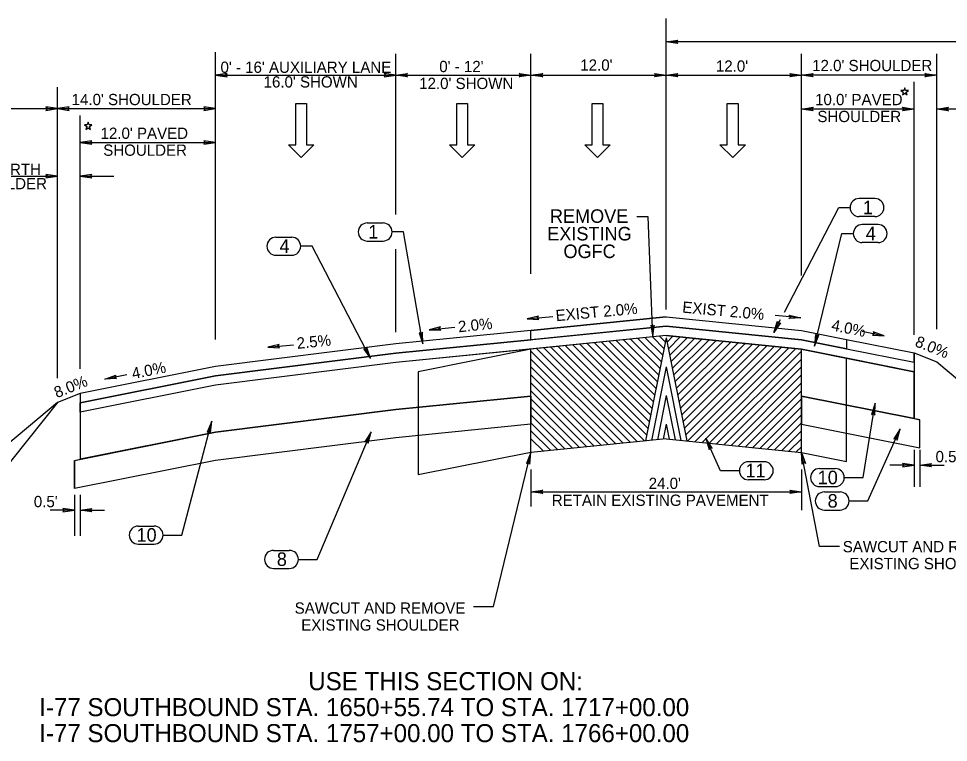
# Model space of a CAD drawing. Extents: x 2003207 to 2014043, y 843846 to 860154.
# Drawn here: x 2013658.4 to 2013740.9, y 844586.8 to 844651 of the extents above; entities that cross this region are included whole.
import ezdxf

# ---------------------------------------------------------------- set-up
doc = ezdxf.new("R2010")
doc.units = 0
for name, color, linetype in [('RD_EX_Road', 7, 'Continuous'), ('RD_EX_Road_txCode', 7, 'Continuous'), ('RD_QTY_Base_Course', 7, 'Continuous'), ('RD_QTY_ConcPave', 7, 'Continuous'), ('RD_QTY_Intermediate', 7, 'Continuous'), ('RD_QTY_PermVeg', 7, 'Continuous'), ('RD_QTY_Surf_Course', 7, 'Continuous'), ('RD_TX_Misc2', 7, 'Continuous'), ('RD_TX_TypSect', 7, 'Continuous')]:
    doc.layers.add(name, color=color, linetype=linetype)

msp = doc.modelspace()

# ---------------------------------------------------------------- linework, layer by layer
at = {"layer": 'RD_EX_Road'}
for p, q in [((2013709.505, 844622.215), (2013714.742, 844616.978)), ((2013710.148, 844622.279), (2013714.86, 844617.567)), ((2013710.79, 844622.344), (2013714.978, 844618.156)), ((2013711.433, 844622.408), (2013715.096, 844618.745)), ((2013712.076, 844622.472), (2013715.214, 844619.335)), ((2013712.719, 844622.536), (2013715.332, 844619.924)), ((2013713.362, 844622.601), (2013715.449, 844620.513)), ((2013714.005, 844622.665), (2013715.567, 844621.102)), ((2013715.875, 844622.64), (2013714.047, 844613.503)), ((2013714.647, 844622.729), (2013715.685, 844621.692)), ((2013715.29, 844622.794), (2013715.803, 844622.281)), ((2013715.875, 844622.852), (2013719.031, 844622.536)), ((2013715.875, 844622.64), (2013717.702, 844613.503)), ((2013716.46, 844622.794), (2013715.947, 844622.281)), ((2013717.102, 844622.729), (2013716.065, 844621.692)), ((2013717.745, 844622.665), (2013716.183, 844621.102)), ((2013718.388, 844622.601), (2013716.3, 844620.513)), ((2013719.031, 844622.536), (2013716.418, 844619.924)), ((2013719.674, 844622.472), (2013716.536, 844619.335)), ((2013720.317, 844622.408), (2013716.654, 844618.745)), ((2013720.959, 844622.344), (2013716.772, 844618.156)), ((2013721.602, 844622.279), (2013716.89, 844617.567)), ((2013722.245, 844622.215), (2013717.007, 844616.978)), ((2013703.875, 844621.652), (2013693.875, 844619.652)), ((2013706.291, 844621.894), (2013703.875, 844621.652)), ((2013703.875, 844612.485), (2013703.875, 844621.652)), ((2013703.875, 844621.481), (2013712.053, 844613.303)), ((2013704.362, 844621.701), (2013712.696, 844613.367)), ((2013705.005, 844621.765), (2013713.338, 844613.432)), ((2013705.648, 844621.829), (2013713.981, 844613.496)), ((2013706.291, 844621.894), (2013714.153, 844614.031)), ((2013706.933, 844621.958), (2013714.271, 844614.62)), ((2013707.576, 844622.022), (2013714.387, 844615.212)), ((2013708.219, 844622.086), (2013714.505, 844615.801)), ((2013708.862, 844622.151), (2013714.623, 844616.39)), ((2013722.888, 844622.151), (2013717.125, 844616.388)), ((2013723.531, 844622.086), (2013717.243, 844615.799)), ((2013724.173, 844622.022), (2013717.361, 844615.21)), ((2013724.816, 844621.958), (2013717.479, 844614.62)), ((2013725.459, 844621.894), (2013717.597, 844614.031)), ((2013726.102, 844621.829), (2013717.769, 844613.496)), ((2013726.745, 844621.765), (2013718.411, 844613.432)), ((2013727.388, 844621.701), (2013719.054, 844613.367)), ((2013727.875, 844621.481), (2013719.697, 844613.303)), ((2013727.875, 844612.485), (2013727.875, 844621.652)), ((2013727.875, 844621.652), (2013731.875, 844620.852)), ((2013703.875, 844620.774), (2013711.41, 844613.239)), ((2013727.875, 844620.774), (2013720.34, 844613.239)), ((2013731.875, 844611.685), (2013731.875, 844620.852)), ((2013703.875, 844620.067), (2013710.767, 844613.175)), ((2013715.875, 844620.091), (2013714.568, 844613.555)), ((2013715.875, 844620.091), (2013717.182, 844613.555)), ((2013727.875, 844620.067), (2013720.983, 844613.175)), ((2013693.875, 844619.652), (2013693.875, 844610.485)), ((2013703.875, 844619.36), (2013710.124, 844613.11)), ((2013727.875, 844619.36), (2013721.626, 844613.11)), ((2013703.875, 844618.653), (2013709.481, 844613.046)), ((2013727.875, 844618.653), (2013722.268, 844613.046)), ((2013703.875, 844617.945), (2013708.839, 844612.982)), ((2013703.875, 844617.238), (2013708.196, 844612.917)), ((2013715.875, 844617.541), (2013715.088, 844613.607)), ((2013715.875, 844617.541), (2013716.662, 844613.607)), ((2013727.875, 844617.945), (2013722.911, 844612.982)), ((2013727.875, 844617.238), (2013723.554, 844612.917)), ((2013703.875, 844616.531), (2013707.553, 844612.853)), ((2013727.875, 844616.531), (2013724.197, 844612.853)), ((2013703.875, 844615.824), (2013706.91, 844612.789)), ((2013727.875, 844615.824), (2013724.84, 844612.789)), ((2013703.875, 844615.117), (2013706.267, 844612.725)), ((2013715.875, 844614.992), (2013715.608, 844613.659)), ((2013715.875, 844614.992), (2013716.142, 844613.659)), ((2013727.875, 844615.117), (2013725.482, 844612.725)), ((2013703.875, 844614.41), (2013705.624, 844612.66)), ((2013727.875, 844614.41), (2013726.125, 844612.66)), ((2013703.875, 844613.703), (2013704.982, 844612.596)), ((2013715.875, 844613.685), (2013703.875, 844612.485)), ((2013715.875, 844613.685), (2013727.875, 844612.485)), ((2013727.875, 844613.703), (2013726.768, 844612.596)), ((2013703.875, 844612.485), (2013693.875, 844610.485)), ((2013727.875, 844612.996), (2013727.411, 844612.532)), ((2013727.875, 844612.485), (2013731.875, 844611.685))]:
    msp.add_line(p, q, dxfattribs=at)
at = {"layer": 'RD_QTY_Base_Course'}
for p, q in [((2013691.875, 844616.285), (2013675.875, 844614.285)), ((2013703.875, 844614.985), (2013691.875, 844613.785)), ((2013727.875, 844614.985), (2013738.375, 844612.885)), ((2013737.875, 844615.485), (2013738.375, 844615.385)), ((2013738.375, 844612.885), (2013738.375, 844615.385)), ((2013738.375, 844612.885), (2013738.375, 844615.385)), ((2013675.875, 844614.285), (2013663.875, 844611.885)), ((2013691.875, 844613.785), (2013675.875, 844611.785)), ((2013738.375, 844612.885), (2013738.375, 844612.885)), ((2013738.375, 844612.885), (2013738.375, 844612.885)), ((2013738.375, 844612.885), (2013738.375, 844612.885)), ((2013663.375, 844611.785), (2013663.875, 844611.885)), ((2013675.875, 844611.785), (2013663.375, 844609.285)), ((2013663.375, 844611.785), (2013663.375, 844609.285))]:
    msp.add_line(p, q, dxfattribs=at)
msp.add_lwpolyline([(2013703.875, 844617.485), (2013703.875, 844614.985), (2013691.875, 844613.785), (2013675.875, 844611.785), (2013663.375, 844609.285), (2013663.375, 844611.785), (2013675.875, 844614.285), (2013691.875, 844616.285)], close=True, dxfattribs=at)
msp.add_lwpolyline([(2013738.375, 844615.385), (2013731.875, 844616.667), (2013727.875, 844617.485), (2013727.875, 844614.985), (2013738.375, 844612.885)], dxfattribs=at)
at = {"layer": 'RD_QTY_ConcPave'}
for p, q in [((2013703.875, 844621.652), (2013691.875, 844620.452)), ((2013703.875, 844621.652), (2013703.875, 844621.652)), ((2013737.875, 844621.319), (2013737.875, 844619.652)), ((2013691.875, 844620.452), (2013691.875, 844620.452)), ((2013737.875, 844615.485), (2013737.875, 844619.652)), ((2013703.875, 844617.485), (2013691.875, 844616.285)), ((2013691.875, 844616.285), (2013703.875, 844617.485)), ((2013727.875, 844617.485), (2013737.875, 844615.485)), ((2013663.875, 844616.052), (2013663.875, 844611.885))]:
    msp.add_line(p, q, dxfattribs=at)
for points in [[(2013703.875, 844617.485), (2013703.875, 844617.617), (2013703.875, 844618.324), (2013703.875, 844621.652)], [(2013691.875, 844620.452), (2013675.875, 844618.452), (2013663.875, 844616.052), (2013663.875, 844611.885), (2013675.875, 844614.285), (2013691.875, 844616.285)]]:
    msp.add_lwpolyline(points, dxfattribs=at)
msp.add_lwpolyline([(2013727.875, 844621.652), (2013737.875, 844619.652), (2013737.875, 844615.485), (2013727.875, 844617.485)], close=True, dxfattribs=at)
at = {"layer": 'RD_QTY_Intermediate'}
for p, q in [((2013715.875, 844622.852), (2013703.875, 844621.652)), ((2013715.875, 844622.852), (2013727.875, 844621.652)), ((2013703.875, 844621.652), (2013691.875, 844620.452)), ((2013727.875, 844621.652), (2013731.875, 844620.852)), ((2013731.875, 844620.852), (2013737.875, 844619.652)), ((2013691.875, 844620.452), (2013675.875, 844618.452)), ((2013737.875, 844620.485), (2013737.875, 844619.652)), ((2013675.875, 844618.452), (2013663.875, 844616.052)), ((2013663.875, 844616.885), (2013663.875, 844616.052))]:
    msp.add_line(p, q, dxfattribs=at)
msp.add_lwpolyline([(2013727.875, 844621.652), (2013715.875, 844622.852), (2013691.875, 844620.452), (2013675.875, 844618.452), (2013663.875, 844616.052), (2013663.875, 844616.885), (2013675.875, 844619.285), (2013691.875, 844621.285), (2013715.875, 844623.685), (2013727.875, 844622.485), (2013731.875, 844621.685), (2013737.875, 844620.485), (2013737.875, 844619.652), (2013731.875, 844620.852)], close=True, dxfattribs=at)
at = {"layer": 'RD_QTY_PermVeg'}
for p, q in [((2013737.875, 844621.319), (2013739.875, 844620.519)), ((2013739.875, 844620.519), (2013771.875, 844593.852)), ((2013663.875, 844617.719), (2013661.875, 844616.919)), ((2013661.875, 844616.919), (2013637.875, 844596.919)), ((2013661.875, 844616.919), (2013637.875, 844586.919))]:
    msp.add_line(p, q, dxfattribs=at)
at = {"layer": 'RD_QTY_Surf_Course'}
for p, q in [((2013715.875, 844624.519), (2013703.875, 844623.319)), ((2013715.875, 844624.519), (2013727.875, 844623.319)), ((2013703.875, 844623.319), (2013691.875, 844622.119)), ((2013715.875, 844623.685), (2013703.875, 844622.485)), ((2013715.875, 844623.685), (2013727.875, 844622.485)), ((2013727.875, 844623.319), (2013731.875, 844622.519)), ((2013703.875, 844622.485), (2013691.875, 844621.285)), ((2013727.875, 844622.485), (2013731.875, 844621.685)), ((2013731.875, 844622.519), (2013737.875, 844621.319)), ((2013691.875, 844622.119), (2013675.875, 844620.119)), ((2013731.875, 844621.685), (2013737.875, 844620.485)), ((2013691.875, 844621.285), (2013675.875, 844619.285)), ((2013737.875, 844620.485), (2013737.875, 844621.319)), ((2013675.875, 844620.119), (2013663.875, 844617.719)), ((2013675.875, 844619.285), (2013663.875, 844616.885)), ((2013663.875, 844617.719), (2013663.875, 844616.885))]:
    msp.add_line(p, q, dxfattribs=at)
for points in [[(2013703.875, 844622.485), (2013703.875, 844623.319), (2013715.875, 844624.519), (2013727.875, 844623.319), (2013731.875, 844622.519), (2013731.875, 844621.685), (2013727.875, 844622.485), (2013715.875, 844623.685)], [(2013703.875, 844623.319), (2013691.875, 844622.119), (2013675.875, 844620.119), (2013663.875, 844617.719), (2013663.875, 844616.885), (2013675.875, 844619.285), (2013691.875, 844621.285), (2013703.875, 844622.485)]]:
    msp.add_lwpolyline(points, close=True, dxfattribs=at)
at = {"layer": 'RD_TX_Misc2'}
for p, q in [((2013734.391, 844635.007), (2013732.991, 844635.007)), ((2013734.391, 844633.407), (2013732.991, 844633.407)), ((2013689.352, 844632.845), (2013690.752, 844632.845)), ((2013734.675, 844632.703), (2013733.275, 844632.703)), ((2013681.243, 844631.576), (2013682.643, 844631.576)), ((2013689.352, 844631.245), (2013690.752, 844631.245)), ((2013734.675, 844631.103), (2013733.275, 844631.103)), ((2013681.243, 844629.976), (2013682.643, 844629.976)), ((2013724.568, 844611.664), (2013723.168, 844611.664)), ((2013729.477, 844611.053), (2013730.877, 844611.053)), ((2013724.568, 844610.064), (2013723.168, 844610.064)), ((2013729.477, 844609.453), (2013730.877, 844609.453)), ((2013729.906, 844608.979), (2013731.306, 844608.979)), ((2013729.906, 844607.379), (2013731.306, 844607.379)), ((2013669.035, 844605.954), (2013670.435, 844605.954)), ((2013669.035, 844604.354), (2013670.435, 844604.354)), ((2013681.035, 844603.8), (2013682.435, 844603.8)), ((2013681.035, 844602.2), (2013682.435, 844602.2))]:
    msp.add_line(p, q, dxfattribs=at)
for centre, start, end in [((2013732.991, 844634.207), 90, 270), ((2013734.391, 844634.207), 270, 90), ((2013689.352, 844632.045), 90, 270), ((2013690.752, 844632.045), 270, 90), ((2013733.275, 844631.903), 90, 270), ((2013734.675, 844631.903), 270, 90), ((2013681.243, 844630.776), 90, 270), ((2013682.643, 844630.776), 270, 90), ((2013723.168, 844610.864), 90, 270), ((2013724.568, 844610.864), 270, 90), ((2013729.477, 844610.253), 90, 270), ((2013730.877, 844610.253), 270, 90), ((2013729.906, 844608.179), 90, 270), ((2013731.306, 844608.179), 270, 90), ((2013669.035, 844605.154), 90, 270), ((2013670.435, 844605.154), 270, 90), ((2013681.035, 844603), 90, 270), ((2013682.435, 844603), 270, 90)]:
    msp.add_arc(centre, 0.8, start, end, dxfattribs=at)
at = {"layer": 'RD_TX_TypSect'}
for p, q in [((2013715.875, 844625.171), (2013715.875, 844650.976)), ((2013771.875, 844648.924), (2013715.875, 844648.924)), ((2013675.875, 844622.505), (2013675.875, 844648.008)), ((2013691.875, 844633.587), (2013691.875, 844647.863)), ((2013703.875, 844628.328), (2013703.875, 844647.863)), ((2013727.875, 844628.198), (2013727.875, 844647.863)), ((2013739.875, 844623.435), (2013739.875, 844647.863)), ((2013675.875, 844645.956), (2013691.875, 844645.956)), ((2013691.875, 844645.956), (2013703.875, 844645.956)), ((2013703.875, 844645.956), (2013715.875, 844645.956)), ((2013715.875, 844645.956), (2013727.875, 844645.956)), ((2013739.875, 844645.956), (2013727.875, 844645.956)), ((2013737.875, 844622.935), (2013737.875, 844645.363)), ((2013661.875, 844619.075), (2013661.875, 844644.894)), ((2013637.875, 844642.987), (2013661.875, 844642.987)), ((2013661.875, 844642.987), (2013675.875, 844642.987)), ((2013737.875, 844642.956), (2013727.875, 844642.956)), ((2013748.662, 844642.956), (2013739.875, 844642.956)), ((2013663.875, 844619.897), (2013663.875, 844642.394)), ((2013663.875, 844639.987), (2013675.875, 844639.987)), ((2013653.088, 844636.987), (2013661.875, 844636.987)), ((2013663.875, 844636.987), (2013666.868, 844636.987)), ((2013691.875, 844623.148), (2013691.875, 844630.522)), ((2013703.53, 844624.335), (2013705.809, 844624.544)), ((2013727.812, 844624.418), (2013725.534, 844624.626)), ((2013694.834, 844623.368), (2013697.111, 844623.595)), ((2013733.273, 844623.233), (2013735.225, 844622.843)), ((2013680.522, 844621.818), (2013682.799, 844622.046)), ((2013668.018, 844619.368), (2013666.067, 844618.978)), ((2013737.875, 844612.728), (2013737.875, 844609.44)), ((2013738.375, 844612.728), (2013738.375, 844609.44)), ((2013703.875, 844610.971), (2013703.875, 844607.68)), ((2013727.875, 844610.971), (2013727.875, 844607.366)), ((2013737.875, 844611.356), (2013735.707, 844611.356)), ((2013738.375, 844611.356), (2013740.542, 844611.356)), ((2013703.875, 844608.998), (2013727.875, 844608.998)), ((2013663.375, 844608.735), (2013663.375, 844605.095)), ((2013663.875, 844608.735), (2013663.875, 844605.095)), ((2013663.375, 844607.364), (2013661.207, 844607.364)), ((2013663.875, 844607.364), (2013666.042, 844607.364))]:
    msp.add_line(p, q, dxfattribs=at)
for points in [[(2013715.875, 844648.924), (2013716.914, 844649.074), (2013716.754, 844648.924), (2013716.914, 844648.775)], [(2013675.875, 844645.956), (2013676.914, 844645.806), (2013676.754, 844645.956), (2013676.914, 844646.106)], [(2013691.875, 844645.956), (2013690.836, 844646.106), (2013690.996, 844645.956), (2013690.836, 844645.806)], [(2013691.875, 844645.956), (2013692.914, 844646.106), (2013692.754, 844645.956), (2013692.914, 844645.806)], [(2013703.875, 844645.956), (2013702.836, 844645.806), (2013702.996, 844645.956), (2013702.836, 844646.106)], [(2013703.875, 844645.956), (2013704.914, 844646.106), (2013704.754, 844645.956), (2013704.914, 844645.806)], [(2013715.875, 844645.956), (2013714.836, 844645.806), (2013714.996, 844645.956), (2013714.836, 844646.106)], [(2013715.875, 844645.956), (2013716.914, 844646.106), (2013716.754, 844645.956), (2013716.914, 844645.806)], [(2013727.875, 844645.956), (2013726.836, 844645.806), (2013726.996, 844645.956), (2013726.836, 844646.106)], [(2013727.875, 844645.956), (2013728.914, 844646.106), (2013728.754, 844645.956), (2013728.914, 844645.806)], [(2013739.875, 844645.956), (2013738.836, 844645.806), (2013738.996, 844645.956), (2013738.836, 844646.106)], [(2013737.37, 844644.594), (2013737.115, 844644.594), (2013737.037, 844644.836), (2013736.958, 844644.594), (2013736.704, 844644.594), (2013736.91, 844644.444), (2013736.831, 844644.202), (2013737.037, 844644.352), (2013737.243, 844644.202), (2013737.164, 844644.444)], [(2013661.875, 844642.987), (2013660.836, 844643.137), (2013660.996, 844642.987), (2013660.836, 844642.837)], [(2013661.875, 844642.987), (2013662.914, 844642.837), (2013662.754, 844642.987), (2013662.914, 844643.137)], [(2013675.875, 844642.987), (2013674.836, 844643.137), (2013674.996, 844642.987), (2013674.836, 844642.837)], [(2013683.005, 844643.445), (2013683.965, 844643.445), (2013683.965, 844639.777), (2013684.616, 844639.777), (2013683.485, 844638.645), (2013682.353, 844639.777), (2013683.005, 844639.777)], [(2013697.293, 844643.445), (2013698.253, 844643.445), (2013698.253, 844639.777), (2013698.905, 844639.777), (2013697.773, 844638.645), (2013696.642, 844639.777), (2013697.293, 844639.777)], [(2013709.293, 844643.445), (2013710.253, 844643.445), (2013710.253, 844639.777), (2013710.905, 844639.777), (2013709.773, 844638.645), (2013708.642, 844639.777), (2013709.293, 844639.777)], [(2013721.293, 844643.445), (2013722.253, 844643.445), (2013722.253, 844639.777), (2013722.905, 844639.777), (2013721.773, 844638.645), (2013720.642, 844639.777), (2013721.293, 844639.777)], [(2013727.875, 844642.956), (2013728.914, 844643.106), (2013728.754, 844642.956), (2013728.914, 844642.806)], [(2013737.875, 844642.956), (2013736.836, 844642.806), (2013736.996, 844642.956), (2013736.836, 844643.106)], [(2013739.875, 844642.956), (2013740.914, 844643.106), (2013740.754, 844642.956), (2013740.914, 844642.806)], [(2013664.917, 844641.542), (2013664.663, 844641.542), (2013664.584, 844641.784), (2013664.505, 844641.542), (2013664.251, 844641.542), (2013664.457, 844641.393), (2013664.378, 844641.151), (2013664.584, 844641.3), (2013664.79, 844641.151), (2013664.711, 844641.393)], [(2013663.875, 844639.987), (2013664.914, 844639.837), (2013664.754, 844639.987), (2013664.914, 844640.137)], [(2013675.875, 844639.987), (2013674.836, 844640.137), (2013674.996, 844639.987), (2013674.836, 844639.837)], [(2013661.875, 844636.987), (2013660.836, 844637.137), (2013660.996, 844636.987), (2013660.836, 844636.837)], [(2013663.875, 844636.987), (2013664.914, 844636.837), (2013664.754, 844636.987), (2013664.914, 844637.137)], [(2013727.812, 844624.418), (2013726.764, 844624.363), (2013726.937, 844624.498), (2013726.791, 844624.662)], [(2013703.53, 844624.335), (2013704.578, 844624.281), (2013704.405, 844624.415), (2013704.551, 844624.579)], [(2013725.413, 844623.133), (2013725.76, 844624.123), (2013725.819, 844623.912), (2013726.026, 844623.984)], [(2013694.271, 844622.112), (2013694.242, 844623.161), (2013694.122, 844622.978), (2013693.947, 844623.11)], [(2013694.834, 844623.368), (2013695.883, 844623.322), (2013695.708, 844623.455), (2013695.853, 844623.62)], [(2013714.689, 844622.733), (2013714.805, 844623.776), (2013714.66, 844623.612), (2013714.505, 844623.767)], [(2013735.225, 844622.843), (2013734.235, 844623.194), (2013734.363, 844623.016), (2013734.177, 844622.9)], [(2013729.02, 844621.912), (2013729.413, 844622.886), (2013729.229, 844622.766), (2013729.122, 844622.957)], [(2013680.522, 844621.818), (2013681.571, 844621.772), (2013681.397, 844621.905), (2013681.541, 844622.07)], [(2013689.645, 844620.807), (2013689.298, 844621.798), (2013689.239, 844621.586), (2013689.032, 844621.659)], [(2013666.067, 844618.978), (2013667.056, 844619.329), (2013666.929, 844619.151), (2013667.115, 844619.035)], [(2013734.404, 844616.847), (2013734.091, 844615.845), (2013734.264, 844615.979), (2013734.387, 844615.797)], [(2013675.564, 844615.257), (2013675.154, 844614.291), (2013675.34, 844614.408), (2013675.444, 844614.215)], [(2013689.682, 844614.315), (2013689.139, 844613.416), (2013689.34, 844613.505), (2013689.416, 844613.3)], [(2013736.648, 844614.591), (2013736.086, 844613.705), (2013736.288, 844613.789), (2013736.36, 844613.582)], [(2013719.405, 844613.757), (2013719.691, 844612.747), (2013719.763, 844612.954), (2013719.965, 844612.869)], [(2013703.875, 844612.485), (2013703.484, 844611.512), (2013703.667, 844611.632), (2013703.775, 844611.441)], [(2013727.875, 844612.485), (2013728.221, 844611.495), (2013728.043, 844611.623), (2013727.927, 844611.437)], [(2013737.875, 844611.356), (2013736.836, 844611.506), (2013736.996, 844611.356), (2013736.836, 844611.206)], [(2013738.375, 844611.356), (2013739.414, 844611.506), (2013739.254, 844611.356), (2013739.414, 844611.206)], [(2013703.875, 844608.998), (2013704.914, 844609.148), (2013704.754, 844608.998), (2013704.914, 844608.848)], [(2013727.875, 844608.998), (2013726.836, 844608.848), (2013726.996, 844608.998), (2013726.836, 844609.148)], [(2013663.375, 844607.364), (2013662.336, 844607.514), (2013662.496, 844607.364), (2013662.336, 844607.214)], [(2013663.875, 844607.364), (2013664.914, 844607.514), (2013664.754, 844607.364), (2013664.914, 844607.214)]]:
    msp.add_lwpolyline(points, close=True, dxfattribs=at)
for points in [[(2013726.356, 844624.943), (2013731.182, 844634.207), (2013732.191, 844634.207)], [(2013714.689, 844622.733), (2013714.267, 844633.386), (2013713.258, 844633.386)], [(2013694.271, 844622.112), (2013692.561, 844632.045), (2013691.552, 844632.045)], [(2013729.02, 844621.912), (2013731.466, 844631.903), (2013732.475, 844631.903)], [(2013689.645, 844620.807), (2013684.452, 844630.776), (2013683.443, 844630.776)], [(2013725.413, 844623.133), (2013726.018, 844624.293)], [(2013731.677, 844610.253), (2013733.343, 844610.253), (2013734.404, 844616.847)], [(2013671.235, 844605.154), (2013672.9, 844605.154), (2013675.564, 844615.257)], [(2013683.235, 844603), (2013684.9, 844603), (2013689.682, 844614.315)], [(2013732.106, 844608.179), (2013733.771, 844608.179), (2013736.648, 844614.591)], [(2013722.368, 844610.864), (2013720.703, 844610.864), (2013719.405, 844613.757)], [(2013698.772, 844598.808), (2013700.547, 844598.808), (2013703.875, 844612.485)], [(2013731.246, 844604.145), (2013729.471, 844604.145), (2013727.875, 844612.485)]]:
    msp.add_lwpolyline(points, dxfattribs=at)

# ---------------------------------------------------------------- texts
at = {"layer": 'RD_EX_Road_txCode'}
for s, p in [('USE THIS SECTION ON:', (2013684.116, 844591.395)), ('I-77 SOUTHBOUND STA. 1650+55.74 TO STA. 1717+00.00', (2013660.242, 844589.089)), ('I-77 SOUTHBOUND STA. 1757+00.00 TO STA. 1766+00.00', (2013660.242, 844586.784))]:
    msp.add_text(s, height=1.6, dxfattribs=at).set_placement(p)
at = {"layer": 'RD_TX_Misc2'}
for s, p in [('1', (2013733.33, 844633.622)), ('REMOVE ', (2013705.557, 844632.855)), ('1', (2013689.441, 844631.461)), ('EXISTING ', (2013705.319, 844631.293)), ('4', (2013733.579, 844631.318)), ('4', (2013681.557, 844630.191)), ('OGFC', (2013706.757, 844629.73)), ('11', (2013722.908, 844610.279)), ('10', (2013729.315, 844609.669)), ('8', (2013730.197, 844607.594)), ('10', (2013668.872, 844604.569)), ('8', (2013681.326, 844602.416))]:
    msp.add_text(s, height=1.2, dxfattribs=at).set_placement(p)
at = {"layer": 'RD_TX_TypSect'}
for s, p in [("0' - 16' AUXILIARY LANE", (2013676.329, 844646.16)), ("0' - 12'", (2013695.739, 844646.227)), ("12.0'", (2013708.252, 844646.355)), ("12.0'", (2013720.283, 844646.264)), ("12.0' SHOULDER", (2013728.824, 844646.313)), ("16.0' SHOWN", (2013680.152, 844644.86)), ("12.0' SHOWN", (2013693.956, 844644.727)), ("14.0' SHOULDER", (2013663.119, 844643.298)), ("10.0' PAVED", (2013729.085, 844643.294)), ('SHOULDER', (2013729.29, 844641.794)), ("12.0' PAVED", (2013665.687, 844640.305)), ('SHOULDER', (2013665.923, 844638.805)), ("2.0' EARTH", (2013653.384, 844637.101)), ('SHOULDER', (2013653.502, 844635.833)), ("0.5'", (2013739.773, 844611.62)), ("24.0'", (2013714.321, 844609.245)), ("0.5'", (2013659.764, 844607.627)), ('RETAIN EXISTING PAVEMENT', (2013705.723, 844607.745)), ('SAWCUT AND REMOVE', (2013731.54, 844603.629)), ('EXISTING SHOULDER', (2013732.123, 844602.129)), ('SAWCUT AND REMOVE', (2013682.908, 844598.18)), ('EXISTING SHOULDER', (2013683.49, 844596.68))]:
    msp.add_text(s, height=1, dxfattribs=at).set_placement(p)
for s, rotation, p in [('EXIST 2.0%', 5.2184, (2013706.111, 844624.122)), ('EXIST 2.0%', 354.7816, (2013717.271, 844624.897)), ('2.0% ', 5.71059, (2013697.46, 844623.142)), ('4.0%', 348.69007, (2013730.477, 844623.32)), ('2.5%', 5.71059, (2013683.14, 844621.67)), ('8.0%', 338.19859, (2013737.875, 844621.938)), ('4.0%', 11.30993, (2013668.568, 844618.987)), ('8.0%', 21.80141, (2013661.804, 844617.292))]:
    msp.add_text(s, height=1, rotation=rotation, dxfattribs=at).set_placement(p)

doc.saveas('drawing.dxf')
